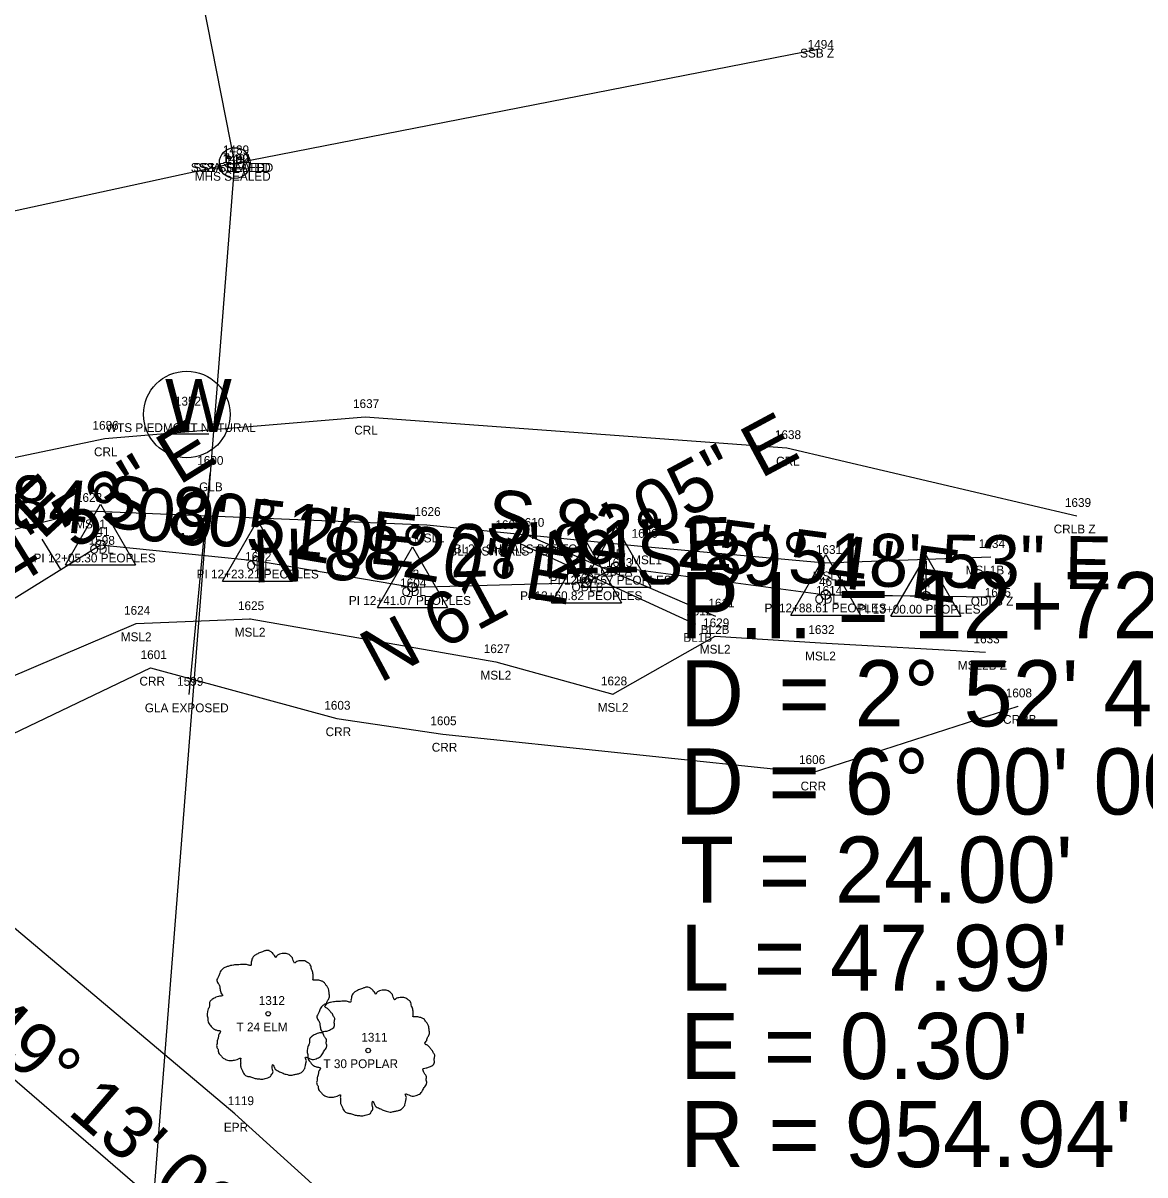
# Model space of a CAD drawing. Extents: x 1812340 to 1815011, y 1177659 to 1180159.
# Drawn here: x 1813793.4 to 1813920.8, y 1178663.1 to 1178793.8 of the extents above; entities that cross this region are included whole.
import ezdxf

# ---------------------------------------------------------------- set-up
doc = ezdxf.new("R2010")
doc.units = 0
for name, color, linetype in [('RD_DTM_BkLn1', 7, 'Continuous'), ('RD_EX_DR_Inlet', 7, 'Continuous'), ('RD_EX_H2O', 7, 'Continuous'), ('RD_EX_H2O_txCode', 7, 'Continuous'), ('RD_EX_Misc', 7, 'Continuous'), ('RD_EX_Misc_txCode', 7, 'Continuous'), ('RD_EX_Road', 7, 'Continuous'), ('RD_EX_Road_txCode', 7, 'Continuous'), ('RD_EX_UT', 7, 'Continuous'), ('RD_EX_UT_txCode', 7, 'Continuous'), ('RD_EX_VEG', 7, 'Continuous'), ('RD_EX_VEG_txCode', 7, 'Continuous'), ('RD_HC_CL', 7, 'Continuous'), ('RD_HC_Data', 7, 'Continuous'), ('RD_HC_Data_Tic', 7, 'Continuous'), ('RD_HC_txCode', 7, 'Continuous'), ('RD_SMD_Locator', 7, 'Continuous'), ('RD_SMD_Misc', 7, 'Continuous')]:
    doc.layers.add(name, color=color, linetype=linetype)

msp = doc.modelspace()

# ---------------------------------------------------------------- linework, layer by layer
at = {"layer": 'RD_DTM_BkLn1'}
for p, q in [((1813848.44, 1178735.38), (1813869.76, 1178725.59)), ((1813850.74, 1178735.64), (1813872.01, 1178726.49))]:
    msp.add_line(p, q, dxfattribs=at)
at = {"layer": 'RD_EX_DR_Inlet'}
for centre, radius in [((1813817.45, 1178777.9), 1.75), ((1813816.78, 1178778.53), 0.175), ((1813818.01, 1178778.46), 0.175), ((1813817.36, 1178777.24), 0.175)]:
    msp.add_circle(centre, radius, dxfattribs=at)
at = {"layer": 'RD_EX_H2O'}
for points in [[(1813767.83, 1178739.34), (1813802.7, 1178746.65), (1813832.24, 1178749.11), (1813880.12, 1178745.59), (1813913.04, 1178737.89)], [(1813860.69, 1178732.09), (1813884.52, 1178728.93), (1813903.65, 1178728.7)], [(1813747.03, 1178677.41), (1813754.34, 1178684.8), (1813763.95, 1178688.13), (1813782.12, 1178708.31), (1813807.89, 1178720.63), (1813829.02, 1178714.89), (1813841.06, 1178713.13), (1813882.92, 1178708.73), (1813906.37, 1178716.29)]]:
    msp.add_lwpolyline(points, dxfattribs=at)
at = {"layer": 'RD_EX_Misc'}
for points in [[(1813573.26, 1178698.61), (1813581.18, 1178685.42), (1813588.27, 1178683.03), (1813621.87, 1178683.41), (1813652.09, 1178681.47), (1813685.62, 1178688.18), (1813723.85, 1178690.46), (1813735.91, 1178692.91), (1813768.22, 1178723.13), (1813784.54, 1178734.4), (1813800.79, 1178738.46), (1813839.24, 1178736.87), (1813863.9, 1178734.39), (1813884.49, 1178732.56), (1813903.28, 1178733.23)], [(1813591.15, 1178668.77), (1813628.98, 1178667.84), (1813655.76, 1178668.83), (1813686.95, 1178670.41), (1813726.51, 1178669.36), (1813738.94, 1178670.71), (1813788.68, 1178718.19), (1813806.25, 1178725.66), (1813819.18, 1178726.19), (1813847.08, 1178721.31), (1813860.38, 1178717.65), (1813871.97, 1178724.25), (1813883.92, 1178723.48), (1813902.67, 1178722.42)]]:
    msp.add_lwpolyline(points, dxfattribs=at)
at = {"layer": 'RD_EX_Road'}
msp.add_lwpolyline([(1814076.45, 1178427.4), (1814038.86, 1178461.87), (1814001.83, 1178496.62), (1813965.15, 1178531.54), (1813928.08, 1178567.1), (1813892.01, 1178601.23), (1813854.54, 1178636.51), (1813817.44, 1178670.03), (1813779.87, 1178701.64)], dxfattribs=at)
at = {"layer": 'RD_EX_UT'}
for p, q in [((1813809.87, 1178747.19), (1813814.5, 1178747.19)), ((1813812.26, 1178717.6), (1813814.64, 1178742.67))]:
    msp.add_line(p, q, dxfattribs=at)
for points in [[(1813817.45, 1178777.9), (1813754.12, 1179098.9), (1813749.26, 1179176.64)], [(1814122.48, 1178351.31), (1814099.73, 1178371.68), (1813807.05, 1178645.14), (1813817.45, 1178777.9), (1813883.81, 1178790.87)], [(1813817.45, 1178777.9), (1813490.2, 1178706.76), (1813294.33, 1178669.42)]]:
    msp.add_lwpolyline(points, dxfattribs=at)
msp.add_circle((1813812, 1178749.39), 4.91, dxfattribs=at)
at = {"layer": 'RD_EX_VEG'}
for centre, radius in [((1813821.24, 1178681.4), 0.25), ((1813821.23, 1178681.38), 0.0001), ((1813832.59, 1178677.23), 0.25), ((1813832.57, 1178677.21), 0.0001)]:
    msp.add_circle(centre, radius, dxfattribs=at)
for points in [[(1813821.37, 1178688.56), (1813821.07, 1178688.59), (1813820.74, 1178688.49), (1813820.49, 1178688.39), (1813820.27, 1178688.31), (1813820.05, 1178688.21), (1813819.75, 1178688.04), (1813819.52, 1178687.84), (1813819.4, 1178687.59), (1813819.35, 1178687.36), (1813819.3, 1178687.09), (1813819.3, 1178686.91), (1813819.17, 1178686.89), (1813819.02, 1178686.91), (1813818.77, 1178686.99), (1813818.52, 1178686.99), (1813818.27, 1178686.99), (1813817.92, 1178686.96), (1813817.57, 1178686.96), (1813817.3, 1178686.91), (1813816.97, 1178686.86), (1813816.6, 1178686.74), (1813816.25, 1178686.61), (1813815.95, 1178686.36), (1813815.7, 1178685.89), (1813815.57, 1178685.54), (1813815.42, 1178685.29), (1813815.57, 1178684.84), (1813815.75, 1178684.49), (1813815.77, 1178684.29), (1813815.85, 1178683.86), (1813815.95, 1178683.64), (1813816.07, 1178683.44), (1813816, 1178683.42), (1813815.62, 1178683.37), (1813815.32, 1178683.27), (1813814.9, 1178683.04), (1813814.67, 1178682.82), (1813814.57, 1178682.49), (1813814.55, 1178682.14), (1813814.45, 1178681.94), (1813814.37, 1178681.67), (1813814.35, 1178681.59), (1813814.3, 1178681.27), (1813814.4, 1178680.82), (1813814.42, 1178680.47), (1813814.55, 1178680.24), (1813814.7, 1178680.07), (1813814.87, 1178679.82), (1813815.27, 1178679.59), (1813815.6, 1178679.49), (1813815.8, 1178679.47), (1813815.62, 1178678.97), (1813815.57, 1178678.62), (1813815.45, 1178678.22), (1813815.45, 1178678.14), (1813815.4, 1178677.67), (1813815.55, 1178677.34), (1813815.62, 1178676.97), (1813815.8, 1178676.74), (1813816.07, 1178676.44), (1813816.4, 1178676.22), (1813816.9, 1178676.09), (1813817.3, 1178676.12), (1813817.87, 1178676.29), (1813818.12, 1178676.37), (1813818.1, 1178676.19), (1813818.12, 1178675.82), (1813818.12, 1178675.39), (1813818.27, 1178675.07), (1813818.37, 1178674.79), (1813818.52, 1178674.54), (1813818.85, 1178674.32), (1813819.25, 1178674.24), (1813819.67, 1178674.09), (1813820.12, 1178674.02), (1813820.62, 1178673.99), (1813821.22, 1178674.14), (1813821.49, 1178674.27), (1813821.59, 1178674.44), (1813821.79, 1178674.82), (1813821.74, 1178675.04), (1813821.77, 1178675.64), (1813821.87, 1178675.47), (1813822.04, 1178675.12), (1813822.54, 1178674.82), (1813822.94, 1178674.64), (1813823.42, 1178674.49), (1813823.72, 1178674.42), (1813824.19, 1178674.49), (1813824.57, 1178674.57), (1813824.94, 1178674.69), (1813825.24, 1178674.97), (1813825.42, 1178675.24), (1813825.47, 1178675.52), (1813825.54, 1178675.89), (1813825.59, 1178676.07)], [(1813825.59, 1178676.07), (1813825.52, 1178676.24), (1813825.47, 1178676.49), (1813825.54, 1178676.47), (1813825.72, 1178676.42), (1813825.99, 1178676.29), (1813826.22, 1178676.22), (1813826.54, 1178676.24), (1813826.82, 1178676.34), (1813827.27, 1178676.62), (1813827.54, 1178677.09), (1813827.82, 1178677.49), (1813827.89, 1178677.82), (1813827.84, 1178678.04), (1813827.82, 1178678.54), (1813827.62, 1178678.79), (1813827.57, 1178678.92), (1813827.47, 1178679.32), (1813827.54, 1178679.37), (1813827.82, 1178679.42), (1813828.19, 1178679.54), (1813828.47, 1178679.67), (1813828.69, 1178679.84), (1813828.77, 1178680.07), (1813828.74, 1178680.47), (1813828.79, 1178680.87), (1813828.72, 1178681.02), (1813828.62, 1178681.17), (1813828.54, 1178681.37), (1813828.39, 1178681.52), (1813828.29, 1178681.67), (1813828.19, 1178681.77), (1813828.07, 1178681.92), (1813827.89, 1178682.04), (1813827.74, 1178682.09), (1813827.69, 1178682.24), (1813827.84, 1178682.44), (1813827.89, 1178682.54), (1813827.92, 1178682.77), (1813828.14, 1178683.12), (1813828.19, 1178683.51), (1813828.14, 1178683.94), (1813828.09, 1178684.21), (1813827.94, 1178684.49), (1813827.74, 1178684.74), (1813827.62, 1178684.91), (1813827.44, 1178685.04), (1813827.12, 1178685.16), (1813826.87, 1178685.21), (1813826.52, 1178685.21), (1813826.32, 1178685.26), (1813826.34, 1178685.31), (1813826.34, 1178685.46), (1813826.34, 1178685.74), (1813826.27, 1178686.19), (1813826.12, 1178686.69), (1813826.12, 1178686.71), (1813826.02, 1178686.96), (1813825.79, 1178687.16), (1813825.62, 1178687.26), (1813825.42, 1178687.39), (1813825.17, 1178687.41), (1813824.87, 1178687.41), (1813824.59, 1178687.36), (1813824.39, 1178687.26), (1813824.22, 1178687.14), (1813824.14, 1178687.29), (1813824.04, 1178687.59), (1813823.99, 1178687.74), (1813823.84, 1178687.91), (1813823.62, 1178688.11), (1813823.17, 1178688.24), (1813822.54, 1178688.16), (1813822.24, 1178687.96), (1813822.09, 1178687.79), (1813822.04, 1178687.91), (1813821.84, 1178688.11), (1813821.74, 1178688.29), (1813821.57, 1178688.41), (1813821.42, 1178688.51), (1813821.32, 1178688.56)], [(1813832.72, 1178684.39), (1813832.42, 1178684.42), (1813832.09, 1178684.32), (1813831.84, 1178684.22), (1813831.62, 1178684.14), (1813831.39, 1178684.04), (1813831.09, 1178683.87), (1813830.87, 1178683.67), (1813830.74, 1178683.42), (1813830.69, 1178683.19), (1813830.64, 1178682.92), (1813830.64, 1178682.74), (1813830.52, 1178682.72), (1813830.37, 1178682.74), (1813830.12, 1178682.82), (1813829.87, 1178682.82), (1813829.62, 1178682.82), (1813829.27, 1178682.79), (1813828.92, 1178682.79), (1813828.65, 1178682.74), (1813828.32, 1178682.69), (1813827.95, 1178682.57), (1813827.6, 1178682.44), (1813827.3, 1178682.19), (1813827.05, 1178681.72), (1813826.92, 1178681.37), (1813826.77, 1178681.12), (1813826.92, 1178680.67), (1813827.1, 1178680.32), (1813827.12, 1178680.12), (1813827.2, 1178679.69), (1813827.3, 1178679.47), (1813827.42, 1178679.27), (1813827.35, 1178679.25), (1813826.97, 1178679.2), (1813826.67, 1178679.1), (1813826.25, 1178678.87), (1813826.02, 1178678.65), (1813825.92, 1178678.32), (1813825.9, 1178677.97), (1813825.8, 1178677.77), (1813825.72, 1178677.5), (1813825.7, 1178677.42), (1813825.65, 1178677.1), (1813825.75, 1178676.65), (1813825.77, 1178676.3), (1813825.9, 1178676.07), (1813826.05, 1178675.9), (1813826.22, 1178675.65), (1813826.62, 1178675.42), (1813826.95, 1178675.32), (1813827.15, 1178675.3), (1813826.97, 1178674.8), (1813826.92, 1178674.45), (1813826.8, 1178674.05), (1813826.8, 1178673.97), (1813826.75, 1178673.5), (1813826.9, 1178673.17), (1813826.97, 1178672.8), (1813827.15, 1178672.57), (1813827.42, 1178672.27), (1813827.75, 1178672.05), (1813828.25, 1178671.92), (1813828.65, 1178671.95), (1813829.22, 1178672.12), (1813829.47, 1178672.2), (1813829.44, 1178672.02), (1813829.47, 1178671.65), (1813829.47, 1178671.22), (1813829.62, 1178670.9), (1813829.72, 1178670.62), (1813829.87, 1178670.37), (1813830.19, 1178670.15), (1813830.59, 1178670.07), (1813831.02, 1178669.92), (1813831.47, 1178669.85), (1813831.97, 1178669.82), (1813832.57, 1178669.97), (1813832.84, 1178670.1), (1813832.94, 1178670.27), (1813833.14, 1178670.65), (1813833.09, 1178670.87), (1813833.12, 1178671.47), (1813833.22, 1178671.3), (1813833.39, 1178670.95), (1813833.89, 1178670.65), (1813834.29, 1178670.47), (1813834.77, 1178670.32), (1813835.07, 1178670.25), (1813835.54, 1178670.32), (1813835.92, 1178670.4), (1813836.29, 1178670.52), (1813836.59, 1178670.8), (1813836.77, 1178671.07), (1813836.82, 1178671.35), (1813836.89, 1178671.72), (1813836.94, 1178671.9)], [(1813836.94, 1178671.9), (1813836.87, 1178672.07), (1813836.82, 1178672.32), (1813836.89, 1178672.3), (1813837.07, 1178672.25), (1813837.34, 1178672.12), (1813837.57, 1178672.05), (1813837.89, 1178672.07), (1813838.17, 1178672.17), (1813838.62, 1178672.45), (1813838.89, 1178672.92), (1813839.17, 1178673.32), (1813839.24, 1178673.65), (1813839.19, 1178673.87), (1813839.17, 1178674.37), (1813838.97, 1178674.62), (1813838.92, 1178674.75), (1813838.82, 1178675.15), (1813838.89, 1178675.2), (1813839.17, 1178675.25), (1813839.54, 1178675.37), (1813839.82, 1178675.5), (1813840.04, 1178675.67), (1813840.11, 1178675.9), (1813840.09, 1178676.3), (1813840.14, 1178676.7), (1813840.07, 1178676.85), (1813839.97, 1178677), (1813839.89, 1178677.2), (1813839.74, 1178677.35), (1813839.64, 1178677.5), (1813839.54, 1178677.6), (1813839.42, 1178677.75), (1813839.24, 1178677.87), (1813839.09, 1178677.92), (1813839.04, 1178678.07), (1813839.19, 1178678.27), (1813839.24, 1178678.37), (1813839.27, 1178678.6), (1813839.49, 1178678.95), (1813839.54, 1178679.34), (1813839.49, 1178679.77), (1813839.44, 1178680.04), (1813839.29, 1178680.32), (1813839.09, 1178680.57), (1813838.97, 1178680.74), (1813838.79, 1178680.87), (1813838.47, 1178680.99), (1813838.22, 1178681.04), (1813837.87, 1178681.04), (1813837.67, 1178681.09), (1813837.69, 1178681.14), (1813837.69, 1178681.29), (1813837.69, 1178681.57), (1813837.62, 1178682.02), (1813837.47, 1178682.52), (1813837.47, 1178682.54), (1813837.37, 1178682.79), (1813837.14, 1178682.99), (1813836.97, 1178683.09), (1813836.77, 1178683.22), (1813836.52, 1178683.24), (1813836.22, 1178683.24), (1813835.94, 1178683.19), (1813835.74, 1178683.09), (1813835.57, 1178682.97), (1813835.49, 1178683.12), (1813835.39, 1178683.42), (1813835.34, 1178683.57), (1813835.19, 1178683.74), (1813834.97, 1178683.94), (1813834.52, 1178684.07), (1813833.89, 1178683.99), (1813833.59, 1178683.79), (1813833.44, 1178683.62), (1813833.39, 1178683.74), (1813833.19, 1178683.94), (1813833.09, 1178684.12), (1813832.92, 1178684.24), (1813832.77, 1178684.34), (1813832.67, 1178684.39)]]:
    msp.add_spline(points, degree=3, dxfattribs=at)
at = {"layer": 'RD_HC_CL'}
for p, q in [((1813785.2, 1178724.07), (1813802.21, 1178734.6)), ((1813802.21, 1178734.6), (1813820.03, 1178732.78)), ((1813820.03, 1178732.78), (1813837.63, 1178729.78)), ((1813857.38, 1178730.32), (1813860.69, 1178732.09)), ((1813860.69, 1178732.09), (1813884.52, 1178728.93)), ((1813837.63, 1178729.78), (1813857.38, 1178730.32)), ((1813884.52, 1178728.93), (1813895.9, 1178728.79)), ((1813850.52, 1178623.8), (1813755.38, 1178705.86))]:
    msp.add_line(p, q, dxfattribs=at)
at = {"layer": 'RD_HC_Data'}
for p, q in [((1813798.24, 1178732.31), (1813802.21, 1178739.19)), ((1813802.21, 1178739.19), (1813806.18, 1178732.31)), ((1813816.06, 1178730.49), (1813820.04, 1178737.37)), ((1813820.04, 1178737.37), (1813824, 1178730.49)), ((1813856.72, 1178729.8), (1813860.69, 1178736.68)), ((1813860.69, 1178736.68), (1813864.66, 1178729.8)), ((1813853.41, 1178728.03), (1813857.38, 1178734.91)), ((1813857.38, 1178734.91), (1813861.35, 1178728.03)), ((1813833.66, 1178727.49), (1813837.64, 1178734.37)), ((1813837.64, 1178734.37), (1813841.6, 1178727.49)), ((1813880.55, 1178726.63), (1813884.52, 1178733.51)), ((1813884.52, 1178733.51), (1813888.49, 1178726.63)), ((1813891.93, 1178726.5), (1813895.91, 1178733.38)), ((1813895.91, 1178733.38), (1813899.87, 1178726.5)), ((1813798.24, 1178732.31), (1813806.18, 1178732.31)), ((1813816.06, 1178730.49), (1813824, 1178730.49)), ((1813856.72, 1178729.8), (1813864.66, 1178729.8)), ((1813833.66, 1178727.49), (1813841.6, 1178727.49)), ((1813853.41, 1178728.03), (1813861.35, 1178728.03)), ((1813880.55, 1178726.63), (1813888.49, 1178726.63)), ((1813891.93, 1178726.5), (1813899.87, 1178726.5))]:
    msp.add_line(p, q, dxfattribs=at)
for centre in [(1813802.21, 1178734.6), (1813820.03, 1178732.78), (1813860.69, 1178732.09), (1813857.38, 1178730.32), (1813837.63, 1178729.78), (1813884.52, 1178728.93), (1813895.9, 1178728.79)]:
    msp.add_circle(centre, 0.529, dxfattribs=at)
at = {"layer": 'RD_HC_Data_Tic'}
for p, q in [((1813797.71, 1178731.81), (1813795.6, 1178735.22)), ((1813895.9, 1178728.79), (1813895.95, 1178732.79))]:
    msp.add_line(p, q, dxfattribs=at)
at = {"layer": 'RD_SMD_Locator'}
for centre in [(1813883.81, 1178790.87), (1813817.45, 1178777.9), (1813817.45, 1178777.9), (1813817.45, 1178777.9), (1813832.24, 1178749.11), (1813802.7, 1178746.65), (1813880.12, 1178745.59), (1813814.64, 1178742.67), (1813800.79, 1178738.46), (1813913.04, 1178737.89), (1813839.24, 1178736.87), (1813848.44, 1178735.38), (1813850.74, 1178735.64), (1813802.21, 1178734.6), (1813802.21, 1178734.6), (1813863.9, 1178734.39), (1813820.03, 1178732.78), (1813820.03, 1178732.78), (1813860.69, 1178732.09), (1813860.69, 1178732.09), (1813884.49, 1178732.56), (1813903.28, 1178733.23), (1813837.63, 1178729.78), (1813837.63, 1178729.78), (1813857.38, 1178730.32), (1813857.38, 1178730.32), (1813884.52, 1178728.93), (1813884.52, 1178728.93), (1813895.9, 1178728.79), (1813903.65, 1178728.7), (1813806.25, 1178725.66), (1813819.18, 1178726.19), (1813869.76, 1178725.59), (1813872.01, 1178726.49), (1813871.97, 1178724.25), (1813883.92, 1178723.48), (1813902.67, 1178722.42), (1813807.89, 1178720.63), (1813847.08, 1178721.31), (1813812.26, 1178717.6), (1813860.38, 1178717.65), (1813906.37, 1178716.29), (1813829.02, 1178714.89), (1813841.06, 1178713.13), (1813882.92, 1178708.73), (1813817.44, 1178670.03)]:
    msp.add_circle(centre, 0.001, dxfattribs=at)

# ---------------------------------------------------------------- texts
at = {"layer": 'RD_EX_H2O_txCode'}
for s, p in [('1637', (1813830.87, 1178750.11)), ('1636', (1813801.3, 1178747.65)), ('CRL', (1813831.01, 1178747.11)), ('1638', (1813878.75, 1178746.59)), ('CRL', (1813801.47, 1178744.65)), ('CRL', (1813878.89, 1178743.59)), ('1639', (1813911.67, 1178738.89)), ('CRLB Z', (1813910.4, 1178735.89)), ('1598', (1813800.87, 1178734.6)), ('ODL', (1813800.97, 1178733.6)), ('1602', (1813818.63, 1178732.78)), ('ODL', (1813818.79, 1178731.78)), ('ODLA', (1813858.95, 1178731.09)), ('1613', (1813859.6, 1178732.09)), ('1604', (1813836.22, 1178729.78)), ('1607', (1813855.97, 1178730.32)), ('ODL', (1813836.39, 1178728.78)), ('ODLB', (1813855.67, 1178729.32)), ('1614', (1813883.43, 1178728.93)), ('1615', (1813902.57, 1178728.7)), ('ODL', (1813883.27, 1178727.93)), ('ODLB Z', (1813900.99, 1178727.7)), ('1601', (1813806.76, 1178721.63)), ('CRR', (1813806.63, 1178718.63)), ('1608', (1813904.96, 1178717.29)), ('1603', (1813827.61, 1178715.89)), ('1605', (1813839.65, 1178714.13)), ('CRRB', (1813904.65, 1178714.29)), ('CRR', (1813827.76, 1178712.89)), ('CRR', (1813839.81, 1178711.13)), ('1606', (1813881.49, 1178709.73)), ('CRR', (1813881.67, 1178706.73))]:
    msp.add_text(s, height=1, dxfattribs=at).set_placement(p)
at = {"layer": 'RD_EX_Misc_txCode'}
for s, p in [('1623', (1813799.42, 1178739.46)), ('1626', (1813837.84, 1178737.87)), ('MSL1', (1813799.33, 1178736.46)), ('1630', (1813862.49, 1178735.39)), ('MSL1', (1813837.78, 1178734.87)), ('1634', (1813901.9, 1178734.23)), ('MSL1', (1813862.44, 1178732.39)), ('1631', (1813883.41, 1178733.56)), ('MSL1B Z', (1813900.4, 1178731.23)), ('MSL1', (1813883.04, 1178730.56)), ('1625', (1813817.81, 1178727.19)), ('1624', (1813804.88, 1178726.66)), ('1629', (1813870.6, 1178725.25)), ('MSL2', (1813804.51, 1178723.66)), ('MSL2', (1813817.44, 1178724.19)), ('1632', (1813882.55, 1178724.48)), ('1633', (1813901.3, 1178723.42)), ('1627', (1813845.71, 1178722.31)), ('MSL2', (1813870.23, 1178722.25)), ('MSL2', (1813882.18, 1178721.48)), ('MSL2', (1813845.34, 1178719.31)), ('MSL2B Z', (1813899.52, 1178720.42)), ('1628', (1813859.01, 1178718.65)), ('MSL2', (1813858.64, 1178715.65))]:
    msp.add_text(s, height=1, dxfattribs=at).set_placement(p)
at = {"layer": 'RD_EX_Road_txCode'}
for s, p in [('1119', (1813816.66, 1178671.03)), ('EPR', (1813816.21, 1178668.03))]:
    msp.add_text(s, height=1, dxfattribs=at).set_placement(p)
at = {"layer": 'RD_EX_UT'}
msp.add_text('W', height=6, dxfattribs=at).set_placement((1813809.54, 1178747.39))
at = {"layer": 'RD_EX_UT_txCode'}
for s, p in [('SSB Z', (1813881.62, 1178789.87)), ('1494', (1813882.47, 1178790.87)), ('1489', (1813816.1, 1178778.9)), ('SS2A SEALED', (1813812.46, 1178776.9)), ('SS1A SEALED', (1813812.75, 1178776.9)), ('SS SEALED', (1813813.42, 1178776.9)), ('1490', (1813816.06, 1178777.9)), ('1492', (1813816.1, 1178777.9)), ('1491', (1813816.39, 1178777.9)), ('MHS SEALED', (1813812.91, 1178775.9)), ('1352', (1813810.65, 1178750.39)), ('WTS PIEDMONT NATURAL', (1813802.83, 1178747.39)), ('1600', (1813813.19, 1178743.67)), ('GLB', (1813813.41, 1178740.67)), ('1599', (1813810.91, 1178718.6)), ('GLA EXPOSED', (1813807.24, 1178715.6))]:
    msp.add_text(s, height=1, dxfattribs=at).set_placement(p)
at = {"layer": 'RD_EX_VEG_txCode'}
for s, p in [('1312', (1813820.17, 1178682.4)), ('T 24 ELM', (1813817.65, 1178679.4)), ('1311', (1813831.81, 1178678.23)), ('T 30 POPLAR', (1813827.51, 1178675.23))]:
    msp.add_text(s, height=1, dxfattribs=at).set_placement(p)
at = {"layer": 'RD_HC_Data'}
for s, rotation, p in [('N 61%%d 46\' 05" E', 28.2319, (1813833.91, 1178718.85)), ('N 58%%d 14\' 53" E', 31.752, (1813769.39, 1178715.47)), ('N 47%%d 21\' 19" E', 42.6448, (1813759.51, 1178701.77)), ('S 84%%d 09\' 51" E', 354.1642, (1813784.12, 1178737.46)), ('S 80%%d 20\' 20" E', 350.3389, (1813802.15, 1178736.84)), ('S 82%%d 25\' 54" E', 352.4318, (1813845.73, 1178735.09)), ('N 88%%d 27\' 11" E', 1.547, (1813819.51, 1178730.3)), ('S 89%%d 18\' 53" E', 359.3146, (1813862.98, 1178730.18)), ('N 49%%d 13\' 06" W', 319.2184, (1813781.4, 1178684.74))]:
    msp.add_text(s, height=6, rotation=rotation, dxfattribs=at).set_placement(p)
for s, p in [('P.I. = 12+72.51', (1813868, 1178724)), ('    = 2%%d 52\' 45" (LT)', (1813868, 1178714)), ('D', (1813868, 1178714)), ('D = 6%%d 00\' 00"', (1813868, 1178704)), ("T = 24.00'", (1813868, 1178694)), ("L = 47.99'", (1813868, 1178684)), ("E = 0.30'", (1813868, 1178674)), ("R = 954.94'", (1813868, 1178664))]:
    msp.add_text(s, height=7.5, dxfattribs=at).set_placement(p)
at = {"layer": 'RD_HC_txCode'}
for s, p in [('41', (1813801.76, 1178735.6)), ('42', (1813819.3, 1178733.78)), ('PI 12+05.30 PEOPLES', (1813794.61, 1178732.6)), ('45', (1813859.95, 1178733.09)), ('44', (1813856.65, 1178731.32)), ('PI 12+23.21 PEOPLES', (1813813.12, 1178730.78)), ('43', (1813836.9, 1178730.78)), ('PI 12+64.57 PEOPLES', (1813853.18, 1178730.09)), ('46', (1813883.76, 1178729.93)), ('47', (1813895.17, 1178729.79)), ('PI 12+41.07 PEOPLES', (1813830.4, 1178727.78)), ('PI 12+60.82 PEOPLES', (1813849.84, 1178728.32)), ('PI 12+88.61 PEOPLES', (1813877.58, 1178726.93)), ('PI 13+00.00 PEOPLES', (1813888.23, 1178726.79))]:
    msp.add_text(s, height=1, dxfattribs=at).set_placement(p)
at = {"layer": 'RD_SMD_Misc'}
for s, p in [('1609', (1813847.03, 1178736.38)), ('1610', (1813849.61, 1178736.64)), ('BL2A SHOALS BOTTOM', (1813842.3, 1178733.64)), ('BL1A SHOALS TOP', (1813841.81, 1178733.38)), ('1611', (1813871.21, 1178727.49)), ('1612', (1813868.68, 1178726.59)), ('BL2B', (1813870.33, 1178724.49)), ('BL1B', (1813868.37, 1178723.59))]:
    msp.add_text(s, height=1, dxfattribs=at).set_placement(p)

doc.saveas('drawing.dxf')
